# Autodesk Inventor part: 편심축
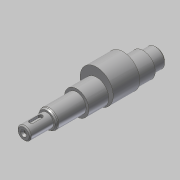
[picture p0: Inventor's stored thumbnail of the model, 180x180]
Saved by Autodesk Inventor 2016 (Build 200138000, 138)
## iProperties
Created: 2019-01
Part Number: 편심축
Material: 강철, 연강
Document SubType Name: Modeling
Designer: mduedu
Density: 7.86 g/cm^3
Appearance: 강철
Mass: 326.791 g
Surface Area: 90.982 cm^2
Volume: 41.5764 cm^3
Author: mduedu
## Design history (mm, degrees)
sketch "스케치1"
  geometry: L1 (0, 0)-(21, 0); L2 (21, 0)-(21, 6); L3 (21, 6)-(0, 6); L4 (0, 6)-(0, 0); L5 (21, 0)-(48, 0); L6 (48, 0)-(48, 8.5); L7 (48, 8.5)-(21, 8.5); L8 (21, 8.5)-(21, 0); L9 (48, 0)-(108, 0); L10 (108, 0)-(108, 11); L11 (108, 11)-(48, 11); L12 (48, 11)-(48, 0); L13 (108, 0)-(120, 0); L14 (120, 0)-(120, 8.5); L15 (120, 8.5)-(108, 8.5); L16 (108, 8.5)-(108, 0)
  constraints: 32 end point, 8 parallel, 4 horizontal, 4 perpendicular
  dimensions: "d0" = 120 distance between parallel lines of L14 L4; "d2" = 12 distance of L14.end L15.end; "d3" = 60 distance of L10.end L11.end; "d4" = 99 distance between parallel lines of L8 L14; "d5" = 12 diameter of L3 L1; "d6" = 17 diameter of L7 L5; "d7" = 17 diameter of L15 L13; "d8" = 22 diameter of L11 L9
revolve "회전1" sketch "스케치1" stored, may be unused: angle "d9" = 90 deg
node "작업 평면1"
sketch "스케치2"
  geometry: C1 r 15 at (0, 4); C2 r 11 at (0, 0) reference; 1 further point
  constraints: 1 centre point, 1 tangent, 1 vertical alignment
  dimensions: "d11" = 4 distance of point (0, 0) C1.centre
extrude "돌출1" join sketch "스케치2" distance "d12" = 24; taper "d13" = 0 deg
node "작업 평면2"
sketch "스케치3" dims "d16" = 12
  geometry: L1 (-4.5, 2)-(3.5, 2); L2 (3.5, 2)-(3.5, -2); L3 (3.5, -2)-(-4.5, -2); L4 (-4.5, -2)-(-4.5, 2); L5 (-10.5, 8.5)-(-10.5, -8.5) reference; 3 further points
  constraints: 8 end point, 2 midpoint, 2 parallel, 2 vertical alignment, 1 horizontal, 1 horizontal alignment, 1 perpendicular, 4 other
  dimensions: "d14" = 4 distance between parallel lines of L3 L1; "d17" = 4 dimension on L5
extrude "돌출2" cut sketch "스케치3" distance "d18" = 2.5; taper "d19" = 0 deg
chamfer "모따기1" distance "d20" = 1.82; stored, may be unused: second distance "d21" = 2, angle "d22" = 30 deg
fillet "모깎기1" dims "d23" = 2
hole "구멍2" diameter "d39" = 3.242; stored, may be unused: countersink angle "d43" = 60 deg, drill point angle "d45" = 118 deg; dims "d37" = 10, "d38" = 10, "d40" = 8, "d41" = 5.51, "d42" = 2, "d44" = 10
sketch "스케치5"
  geometry: L1 (0, 0)-(2, 0); L2 (2, 0)-(2, 1.621); L3 (0, 2.776)-(0, 0); L4 (0, 2.776)-(2, 1.621); L5 (10, 1.621)-(0, 1.621) reference
  constraints: 8 end point, 1 horizontal, 1 parallel, 1 perpendicular, 1 point on line
  dimensions: "d46" = 2 distance between parallel lines of L2 L3; "d48" = 30 deg angle of L4 L1
revolve "회전2" sketch "스케치5" stored, may be unused: angle "d50" = 90 deg
chamfer "모따기2" distance "d25" = 1; stored, may be unused: second distance "d26" = 2, angle "d27" = 30 deg
node "솔리드1"
